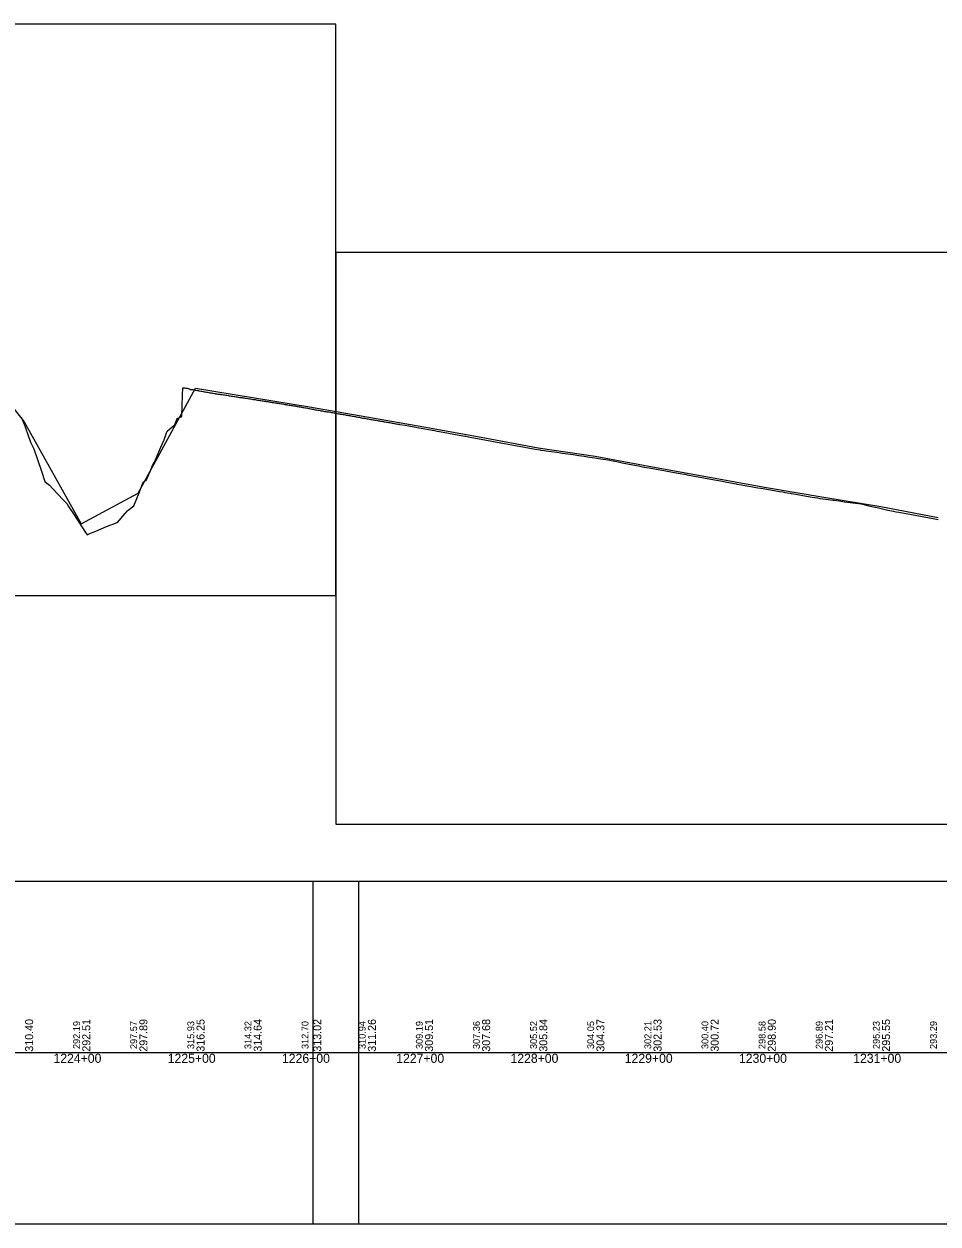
# Model space of a CAD drawing. Extents: x -3627 to 47473, y 2850 to 4350.
# Drawn here: x 9727 to 10527, y 2850 to 3900 of the extents above; entities that cross this region are included whole.
import ezdxf

# ---------------------------------------------------------------- set-up
doc = ezdxf.new("R2010")
doc.units = 0
for name, color, linetype in [('RD_DDB_Profile_EX', 7, 'Continuous'), ('RD_DDB_Profile_PR', 7, 'Continuous'), ('RD_DDB_StaTX', 7, 'Continuous'), ('RD_DDB_StripGrade', 7, 'Continuous'), ('RD_GPK_Profile_Cell', 7, 'Continuous'), ('RD_SHT_ShtClip', 7, 'Continuous')]:
    doc.layers.add(name, color=color, linetype=linetype)

msp = doc.modelspace()

# ---------------------------------------------------------------- linework, layer by layer
at = {"layer": 'RD_DDB_Profile_EX'}
for points in [[(9749.515886, 3496.337675), (9752.128377, 3493.58071), (9756.877853, 3488.566665), (9761.627329, 3483.55072), (9764.693222, 3480.311595), (9766.376806, 3477.73188), (9771.126282, 3470.45594), (9775.875758, 3463.181585), (9780.625235, 3455.90884), (9782.519337, 3453.0091), (9785.637853, 3454.395955), (9786.471518, 3454.804665), (9790.216554, 3456.35073), (9794.873664, 3458.27456), (9799.62314, 3460.23833), (9803.262211, 3461.74435), (9804.372617, 3462.15662), (9807.991063, 3463.50143), (9809.202836, 3463.9494), (9813.871569, 3469.41321), (9817.890275, 3474.11779), (9818.621046, 3474.6561), (9823.537755, 3478.278175), (9828.119998, 3489.8399), (9831.766883, 3499.042285), (9832.869475, 3499.91384), (9834.61096, 3501.2896), (9837.618951, 3508.38502), (9839.893458, 3513.74946), (9841.581948, 3516.716615), (9842.368427, 3518.553745), (9847.117904, 3529.645745), (9849.881463, 3536.098465), (9851.86738, 3541.539955), (9852.651906, 3543.68932), (9856.616856, 3547.10827), (9859.263828, 3549.389485), (9861.366333, 3554.848615), (9865.381285, 3556.42332), (9866.115809, 3575.222235), (9866.442555, 3581.79077), (9867.04793, 3581.73894), (9868.055562, 3581.53661), (9869.038529, 3581.43695), (9870.053319, 3581.23251), (9871.035677, 3580.93611), (9872.051321, 3580.826795), (9873.045729, 3580.326455), (9874.034441, 3580.175715), (9875.052443, 3580.069135), (9875.614762, 3579.98365), (9876.031586, 3579.920055), (9877.030304, 3579.718775), (9878.049961, 3579.51438), (9879.04926, 3579.30988), (9880.029091, 3579.2052), (9880.364238, 3579.13728), (9881.036182, 3579.002515), (9882.035056, 3578.80081), (9883.033843, 3578.64547), (9884.032851, 3578.44388), (9885.113715, 3578.28242), (9886.038881, 3578.18303), (9887.03277, 3577.932635), (9888.031859, 3577.727785), (9889.030794, 3577.572775), (9890.029632, 3577.370955), (9891.028628, 3577.216965), (9892.036065, 3577.013065), (9893.035242, 3576.85566), (9894.028928, 3576.7009), (9894.612667, 3576.581715), (9895.028149, 3576.48914), (9896.027216, 3576.288335), (9897.026492, 3576.18381), (9898.033407, 3576.081695), (9898.904467, 3576.03656), (9899.362144, 3575.944625), (9899.900567, 3575.83829), (9900.901017, 3575.68808), (9901.897154, 3575.53122), (9902.897964, 3575.48105), (9904.11162, 3575.249815), (9904.902888, 3575.128105), (9905.899114, 3574.924795), (9906.900226, 3574.78044), (9907.896244, 3574.58328), (9908.897, 3574.484775), (9909.901371, 3574.32695), (9910.902579, 3574.175755), (9911.898691, 3573.925955), (9912.899535, 3573.77694), (9913.895892, 3573.66859), (9914.896981, 3573.423075), (9915.901668, 3573.318855), (9916.904393, 3573.21504), (9917.900698, 3573.099595), (9918.360049, 3573.052315), (9918.89668, 3572.99696), (9919.897936, 3572.84692), (9920.894352, 3572.691645)], [(9920.894352, 3572.691645), (9921.903859, 3572.489575), (9923.109525, 3572.329075), (9923.659105, 3572.197195), (9924.657812, 3572.00366), (9925.664673, 3571.89951), (9926.663374, 3571.70814), (9927.859002, 3571.49152), (9928.660422, 3571.41018), (9929.659116, 3571.313975), (9930.657805, 3571.11778), (9931.661888, 3570.972785), (9932.660267, 3570.8267), (9933.658955, 3570.674495), (9934.65764, 3570.576045), (9935.656321, 3570.3829), (9936.654716, 3570.13799), (9937.653397, 3570.08606), (9938.660079, 3570.031515), (9939.658763, 3569.737585), (9940.657178, 3569.59201), (9941.655862, 3569.49156), (9942.107431, 3569.289405), (9942.654547, 3569.054875), (9943.653233, 3569.049105), (9944.651917, 3568.901145), (9945.650351, 3568.79877), (9946.856907, 3568.578665), (9947.653176, 3568.460125), (9948.651867, 3568.262905), (9949.650482, 3568.11442), (9950.64917, 3567.96439), (9951.647857, 3567.814365), (9952.654607, 3567.66272), (9953.653081, 3567.51209), (9954.651783, 3567.31415), (9955.650485, 3567.1662), (9956.649191, 3567.01531), (9957.318388, 3566.86822), (9958.317891, 3566.722805), (9959.321665, 3566.62133), (9960.311996, 3566.523925), (9961.315918, 3566.32872), (9962.311471, 3566.13179), (9963.310119, 3565.93361), (9964.305669, 3565.83896), (9965.309549, 3565.592935), (9965.854813, 3565.45898), (9966.305244, 3565.349005), (9967.304061, 3565.198725), (9968.29969, 3565.003235), (9969.303611, 3564.95165), (9970.302427, 3564.752245), (9970.604289, 3564.677875), (9971.298222, 3564.507335), (9972.302307, 3564.30876), (9973.298028, 3564.163485), (9974.297036, 3564.010645), (9975.353765, 3563.80635), (9976.29679, 3563.66614), (9977.287518, 3563.51588), (9978.29171, 3563.31742), (9979.287607, 3563.07137), (9980.291822, 3562.871925), (9981.282419, 3562.719325), (9982.286804, 3562.520175), (9983.460307, 3562.37049), (9984.464694, 3562.2189), (9984.852718, 3562.141965), (9985.460741, 3562.021685), (9986.462123, 3561.82756), (9987.466465, 3561.628405), (9988.462542, 3561.43151), (9989.602194, 3561.25374), (9990.463157, 3561.08116), (9991.459314, 3560.980675), (9992.455547, 3560.7324), (9993.459903, 3560.63029), (9994.456069, 3560.530475), (9995.452388, 3560.281495), (9996.456952, 3560.129335), (9997.453196, 3559.928145), (9998.451957, 3559.77855), (9999.101147, 3559.64793), (9999.456541, 3559.57626), (10000.452922, 3559.425945), (10001.454489, 3559.229795), (10002.459194, 3559.02698), (10003.455574, 3558.875915), (10003.850623, 3558.816295), (10004.451898, 3558.72445), (10005.456792, 3558.520115), (10006.453294, 3558.36826), (10007.449713, 3558.168765), (10008.6001, 3557.935875), (10009.451068, 3557.763625), (10010.456072, 3557.60938), (10011.452607, 3557.45756), (10012.449242, 3557.30675), (10013.454254, 3557.10052), (10014.450846, 3556.99707)], [(9724.990298, 3556.11925), (9727.544092, 3549.90418), (9728.380995, 3547.412705), (9730.924937, 3539.83827), (9732.645753, 3535.05697), (9733.130471, 3534.023665), (9735.531311, 3528.904275), (9737.879948, 3522.407125), (9739.180957, 3518.80778), (9742.629424, 3508.70331), (9745.706574, 3499.590655), (9747.3789, 3498.16303), (9749.515886, 3496.337675)], [(10014.450846, 3556.99707), (10015.452781, 3556.79604), (10016.457782, 3556.64188), (10017.454547, 3556.439345), (10018.099052, 3556.308325), (10018.451362, 3556.239855), (10019.456595, 3556.084215), (10020.539358, 3555.889965), (10021.533127, 3555.692665), (10022.532114, 3555.499785), (10022.848529, 3555.406715), (10023.531172, 3555.20727), (10024.524925, 3555.009135), (10025.523858, 3554.963555), (10026.531284, 3554.864715), (10027.598005, 3554.657005), (10028.511276, 3554.52463), (10029.511221, 3554.32999), (10030.50525, 3554.08052), (10031.505194, 3553.93582), (10032.517634, 3553.78841), (10033.507127, 3553.589095), (10034.507177, 3553.34412), (10035.507054, 3553.24671), (10036.507004, 3553.100555), (10037.096958, 3552.952515), (10037.501098, 3552.85192), (10038.500988, 3552.65302), (10039.50094, 3552.457155), (10040.50309, 3552.353685), (10041.502985, 3552.157325), (10041.846434, 3552.072555), (10042.502941, 3551.9109), (10043.49703, 3551.760135), (10044.496937, 3551.463765), (10045.496894, 3551.465), (10046.595911, 3551.347845), (10047.498957, 3551.21208), (10048.498923, 3551.014295), (10049.493015, 3550.714355), (10050.492935, 3550.61571), (10051.492959, 3550.36771), (10052.487064, 3550.21524), (10053.486994, 3550.11594), (10054.486969, 3549.867045), (10055.521005, 3549.806855), (10056.094863, 3549.70643), (10060.84434, 3548.87202), (10064.048239, 3548.307135), (10065.593816, 3548.0345), (10070.343292, 3547.193505), (10072.987405, 3546.72353), (10075.092769, 3546.34932), (10079.842245, 3545.501935), (10084.591721, 3544.65135), (10085.528852, 3544.482885), (10089.005373, 3543.857995), (10089.341198, 3543.79763), (10094.090674, 3542.94079), (10098.84015, 3542.080805), (10103.589627, 3541.21768), (10108.339103, 3540.35142), (10113.088579, 3539.482025), (10113.993499, 3539.31886), (10116.272012, 3538.88684), (10117.838056, 3538.589185), (10122.587532, 3537.683495), (10127.337009, 3536.774845), (10132.086485, 3535.86323), (10136.835961, 3534.94866), (10141.085013, 3534.12853), (10141.585438, 3534.039905), (10146.334914, 3533.195905), (10147.900887, 3532.91667), (10151.08439, 3532.352135), (10154.170468, 3531.801415), (10155.833867, 3531.50478), (10160.583343, 3530.653635), (10165.332819, 3529.79832), (10170.082296, 3528.938835), (10174.831772, 3528.075185), (10179.061377, 3527.302235), (10179.581248, 3527.23003), (10182.972014, 3526.75252), (10184.330725, 3526.561695), (10189.080201, 3525.89195), (10193.829677, 3525.21952), (10198.579154, 3524.5444), (10203.32863, 3523.8666), (10208.078106, 3523.17875), (10212.827583, 3522.462895), (10215.423454, 3522.0574), (10217.577059, 3521.73063), (10222.326536, 3521.00953), (10227.076012, 3520.287985), (10231.825488, 3519.56599), (10236.574965, 3518.843555), (10240.170596, 3518.287185), (10241.324441, 3518.05617), (10246.073917, 3517.11515), (10250.823394, 3516.166055)], [(10250.823394, 3516.166055), (10255.57287, 3515.216485), (10260.322346, 3514.26644), (10265.071823, 3513.31593), (10269.821299, 3512.364945), (10270.63564, 3512.208435), (10272.124457, 3511.952555), (10274.570775, 3511.530575), (10279.320252, 3510.710425), (10284.069728, 3509.88939), (10288.819204, 3509.067475), (10293.568681, 3508.24468), (10296.745638, 3507.694405), (10298.318157, 3507.403405), (10303.067634, 3506.523415), (10305.652495, 3506.05248), (10307.81711, 3505.65156), (10312.566586, 3504.77014), (10317.316063, 3503.886995), (10322.065539, 3503.00212), (10326.815015, 3502.11552), (10330.363556, 3501.45481), (10331.564492, 3501.2309), (10336.934586, 3500.231155), (10341.063444, 3499.457175), (10345.812921, 3498.56443), (10350.562397, 3497.66926), (10351.571819, 3497.47849), (10355.311873, 3496.768595), (10360.06135, 3495.863885), (10361.660419, 3495.559815), (10364.810826, 3495.03228), (10366.419519, 3494.762125), (10369.560302, 3494.23413), (10374.309779, 3493.43261), (10379.059255, 3492.628), (10383.808732, 3491.82031), (10388.558208, 3491.00954), (10391.362609, 3490.52764), (10393.307684, 3490.195845), (10398.057161, 3489.38253), (10398.886343, 3489.239355), (10402.806637, 3488.565415), (10407.556113, 3487.74575), (10412.30559, 3486.92292), (10417.055066, 3486.09692), (10421.804542, 3485.267755), (10423.834795, 3484.916005), (10426.554019, 3484.557455), (10431.303495, 3483.927995), (10435.208515, 3483.388135), (10436.052971, 3483.275565), (10440.802448, 3482.638695), (10445.551924, 3481.99808), (10450.3014, 3481.353725), (10455.050877, 3480.705635), (10459.982099, 3480.006455), (10464.549829, 3478.990525), (10465.567137, 3478.78741), (10469.299306, 3477.95339), (10474.048782, 3476.8885), (10478.798259, 3475.820085), (10483.547735, 3474.748145), (10488.297211, 3473.672685), (10490.291986, 3473.249685), (10493.046688, 3472.751465), (10497.796164, 3471.88934), (10502.54564, 3471.031925), (10507.295117, 3470.16356), (10512.044593, 3469.29225), (10516.794069, 3468.417995), (10521.543546, 3467.5408), (10527.331218, 3466.473835)]]:
    msp.add_lwpolyline(points, dxfattribs=at)
at = {"layer": 'RD_DDB_Profile_PR'}
msp.add_lwpolyline([(9677.33, 3615.0895), (9727.33, 3552.025), (9777.33, 3462.5545), (9827.33, 3489.4465), (9877.33, 3581.2585), (9927.33, 3573.1875), (9977.33, 3565.1075), (10027.33, 3556.309), (10077.33, 3547.55), (10127.33, 3538.376), (10177.33, 3529.2185), (10227.33, 3521.8495), (10277.33, 3512.654), (10327.33, 3503.6195), (10377.33, 3494.521), (10427.33, 3486.0545), (10477.33, 3477.7505), (10527.33, 3468.074)], dxfattribs=at)
at = {"layer": 'RD_GPK_Profile_Cell'}
msp.add_line((1000, 3000), (46705.077602, 3000), dxfattribs=at)
at = {"layer": 'RD_SHT_ShtClip'}
for points in [[(10000.165, 3400), (10000.165, 3900), (10000.165, 3900), (8500.33, 3900), (8500.33, 3400)], [(11500.165, 3200), (11500.165, 3700), (11500.165, 3700), (10000.33, 3700), (10000.33, 3200)], [(8480.33, 3150), (10020, 3150), (10020, 2850), (8480.33, 2850)], [(9980.33, 3150), (11520, 3150), (11520, 2850), (9980.33, 2850)]]:
    msp.add_lwpolyline(points, close=True, dxfattribs=at)

# ---------------------------------------------------------------- texts
at = {"layer": 'RD_DDB_StaTX'}
for s, p in [('1224+00', (9753.125471, 2991)), ('1225+00', (9853.125471, 2991)), ('1226+00', (9953.125471, 2991)), ('1227+00', (10053.125471, 2991)), ('1228+00', (10153.125471, 2991)), ('1229+00', (10253.125471, 2991)), ('1230+00', (10353.125471, 2991)), ('1231+00', (10453.125471, 2991))]:
    msp.add_text(s, height=8, dxfattribs=at).set_placement(p)
at = {"layer": 'RD_DDB_StripGrade'}
for s, height, p in [('310.40', 7, (9735.33, 3000.75)), ('292.19', 6, (9776.33, 3003.073688)), ('292.51', 7, (9785.33, 3000.75)), ('297.57', 6, (9826.33, 3003.073688)), ('297.89', 7, (9835.33, 3000.75)), ('315.93', 6, (9876.33, 3003.073688)), ('316.25', 7, (9885.33, 3000.75)), ('314.32', 6, (9926.33, 3003.073688)), ('314.64', 7, (9935.33, 3000.75)), ('312.70', 6, (9976.33, 3003.073688)), ('313.02', 7, (9987.503263, 3000.75)), ('310.94', 6, (10026.33, 3003.073688)), ('311.26', 7, (10035.33, 3000.75)), ('309.19', 6, (10076.33, 3003.073688)), ('309.51', 7, (10085.33, 3000.75)), ('307.36', 6, (10126.33, 3003.073688)), ('307.68', 7, (10135.33, 3000.75)), ('305.52', 6, (10176.33, 3003.073688)), ('305.84', 7, (10185.33, 3000.75)), ('304.05', 6, (10226.33, 3003.073688)), ('304.37', 7, (10235.33, 3000.75)), ('302.21', 6, (10276.33, 3003.073688)), ('302.53', 7, (10285.33, 3000.75)), ('300.40', 6, (10326.33, 3003.073688)), ('300.72', 7, (10335.33, 3000.75)), ('298.58', 6, (10376.33, 3003.073688)), ('298.90', 7, (10385.33, 3000.75)), ('296.89', 6, (10426.33, 3003.073688)), ('297.21', 7, (10435.33, 3000.75)), ('295.23', 6, (10476.33, 3003.073688)), ('295.55', 7, (10485.33, 3000.75)), ('293.29', 6, (10526.33, 3003.073688))]:
    msp.add_text(s, height=height, rotation=90, dxfattribs=at).set_placement(p)

doc.saveas('drawing.dxf')
